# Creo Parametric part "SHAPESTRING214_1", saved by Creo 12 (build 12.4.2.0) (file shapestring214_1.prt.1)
Units: Custom; MM, KILOGRAM, SECS

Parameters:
  PTC_WM_ITERATION = "0"
  PTC_WM_VERSION = "-.0"
  PTC_WM_LIFECYCLE_STATE = "In Work"
  PTC_WM_LIFECYCLE = "MO_CADDocument"
  PTC_WM_CREATED_BY = "Maximilian Roepper (Z0017RMS: MO)"
  PTC_WM_CREATED_ON = "18-Sep-26 11:36:42 AM"
  PTC_WM_MODIFIED_BY = "Maximilian Roepper (Z0017RMS: MO)"
  PTC_WM_MODIFIED_ON = "18-Sep-26 11:36:46 AM"
  PDMLINKNUMBER = "PDM000071455235"
  PTC_WM_NAME = "shapestring214_1.prt"
  PTC_WM_NUMBER = "PDM000071455235"

Other parameters: WEIGHT, WEIGHT_FACTOR, WEIGHT_ADD, _MASS_TEMP, _DIFF_TEMP, MC_ERRORS, SUPPLIER

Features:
  1. coordinate system
  2. datum plane "PRT_YZ"
  3. datum plane "PRT_XY"
  4. datum plane "PRT_XZ"
  5. coordinate system
  6. datum axis
  7. datum axis
  8. datum axis
  9. coordinate system
  10. imported feature

Other named items: PRT, SIEMENS_MO, DRW_VIEW_ORG, PRT_X, PRT_Y, PRT_Z, CS0, ROUGH_GROB

Layers: 00_STD_CSYS-KSYS, 01_STD_PLANES-EBENEN, 02_STD_AXES-ACHSEN, 03_STD_CSYS-KSYS, 24_IMPORT_FEAT-IMPORT_KE, INTFCLR

Surfaces: 1 plane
